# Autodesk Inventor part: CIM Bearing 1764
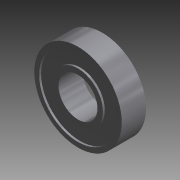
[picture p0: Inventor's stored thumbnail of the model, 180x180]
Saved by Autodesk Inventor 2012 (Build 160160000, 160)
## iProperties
Shininess: 60.0
Length Units: 11272
Angle Units: 11279
Time Units: 11290
Mass Units: 11286
Length Display Precision: 3
Angle Display Precision: 2
Company: FirstCad Library
Created: 2001-10
Part Number: CIM Bearing 1764
Material: Stainless Steel, Austenitic
Document SubType Name: Modeling
Description: 1/2" Dia Bearing
Designer: Ed Sparks
Mass: 29.7504 g
Surface Area: 22.247 cm^2
Volume: 3.7049 cm^3
Density: 8.03 g/cm^3
Density: 0.0
Volumn: 0.0
Area: 0.0
PropertySet Name: Model Information
Control State: 0
Master: False
Checked Out: False
Author: Ed Sparks
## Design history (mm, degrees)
node "Extrusion1" dims "d35" = 7.9375, "d36" = 0
  sketch "Sketch1"
    geometry: C1 r 8.128 at (0, 0); C2 r 6.35 at (0, 0)
    constraints: 2 centre point, 1 coincident
    dimensions: "d32" = 12.7 diameter of C2; "d33" = 16.256 diameter of C1
workplane "Work Plane1"
node "Extrusion2" dims "d39" = 6.6675, "d40" = 0
  sketch "Sketch2"
    geometry: C1 r 12.7 at (0, 0); C2 r 8.128 at (0, 0)
    constraints: 2 centre point, 1 coincident
    dimensions: "d37" = 25.4 diameter of C1; "d38" = 16.256 diameter of C2
node "Extrusion3" dims "d43" = 7.9375, "d44" = 0
  sketch "Sketch3"
    geometry: C1 r 12.7 at (0, 0); C2 r 14.287 at (0, 0)
    constraints: 2 centre point, 1 coincident
    dimensions: "d41" = 25.4 diameter of C1; "d42" = 28.575 diameter of C2
body "Solid1"
other parameters: "d9" = 1.4241 (derived)
